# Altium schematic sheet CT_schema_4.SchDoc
size 454 x 430 mm
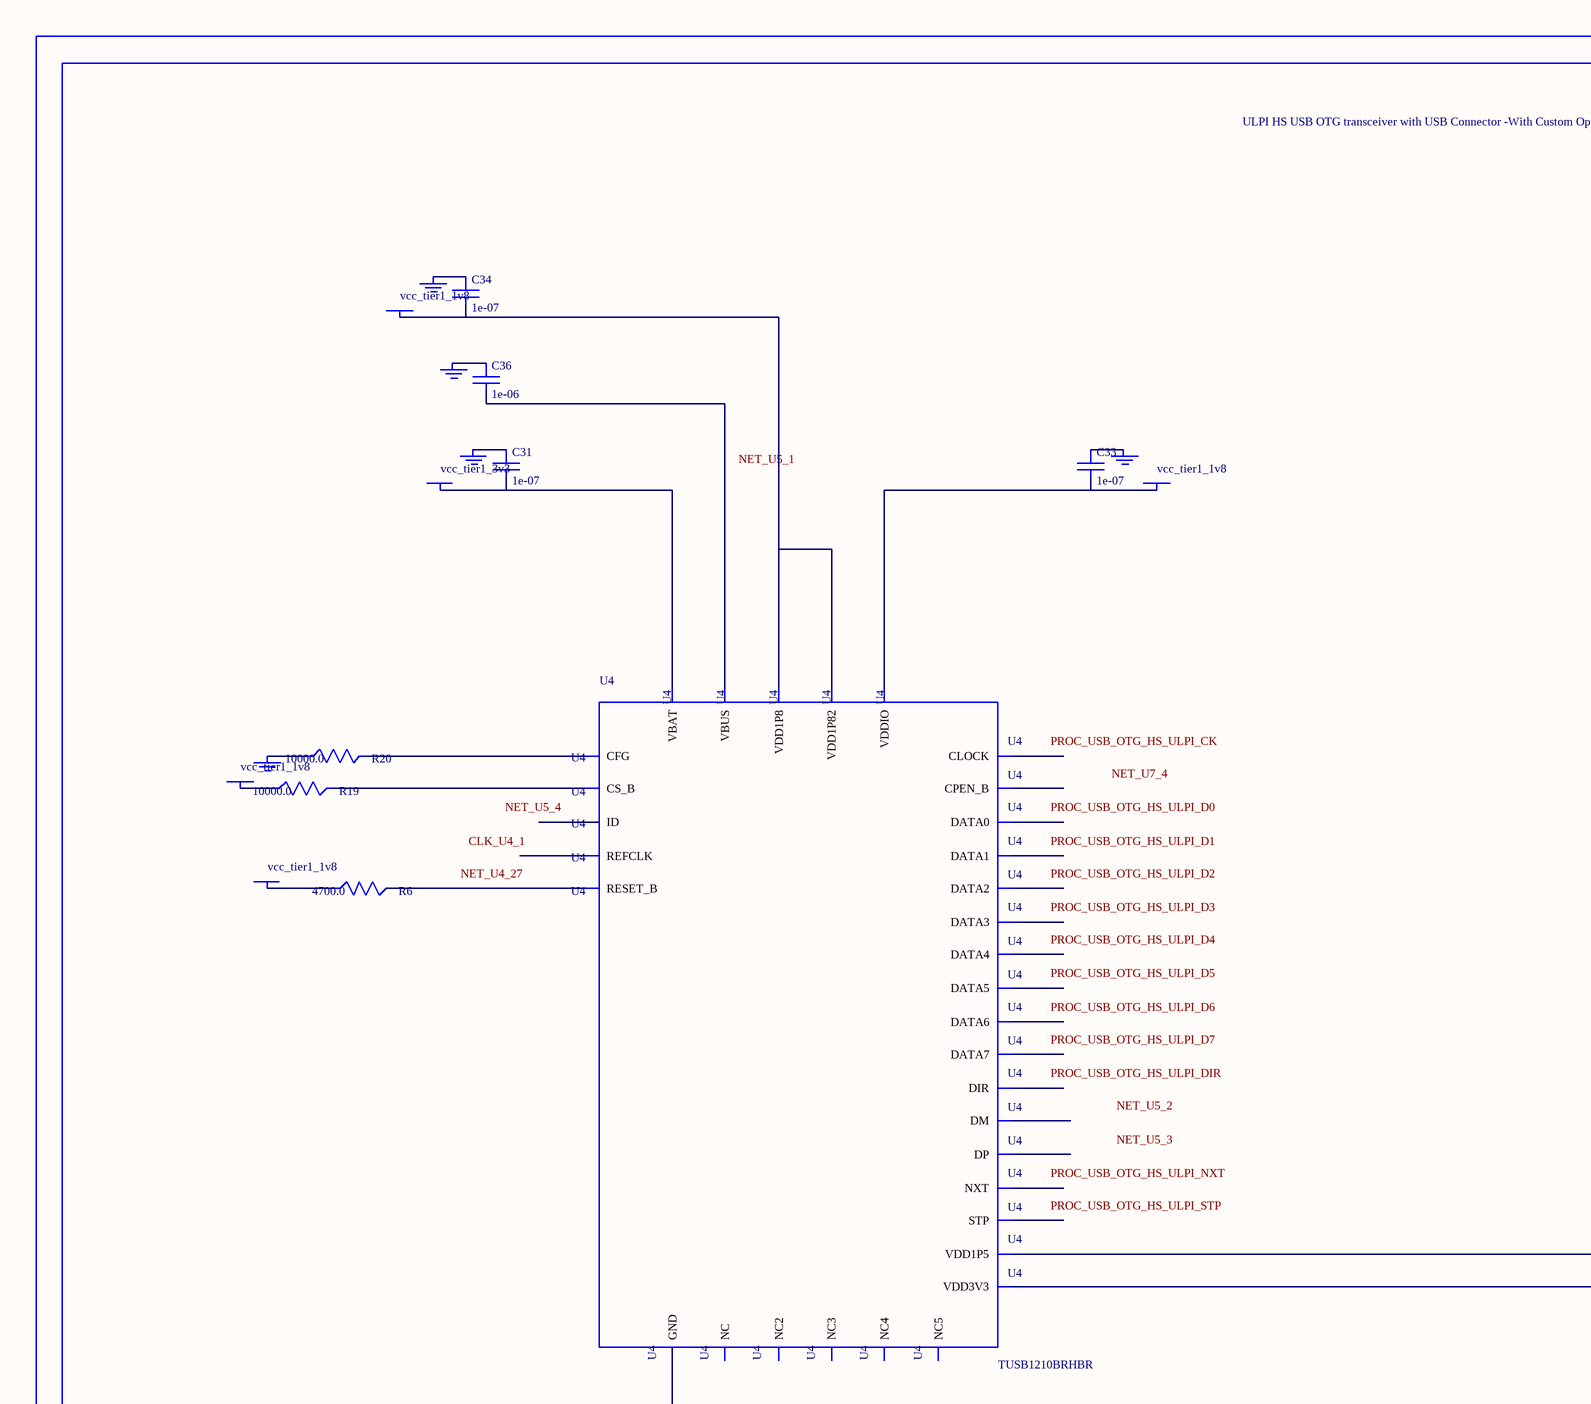
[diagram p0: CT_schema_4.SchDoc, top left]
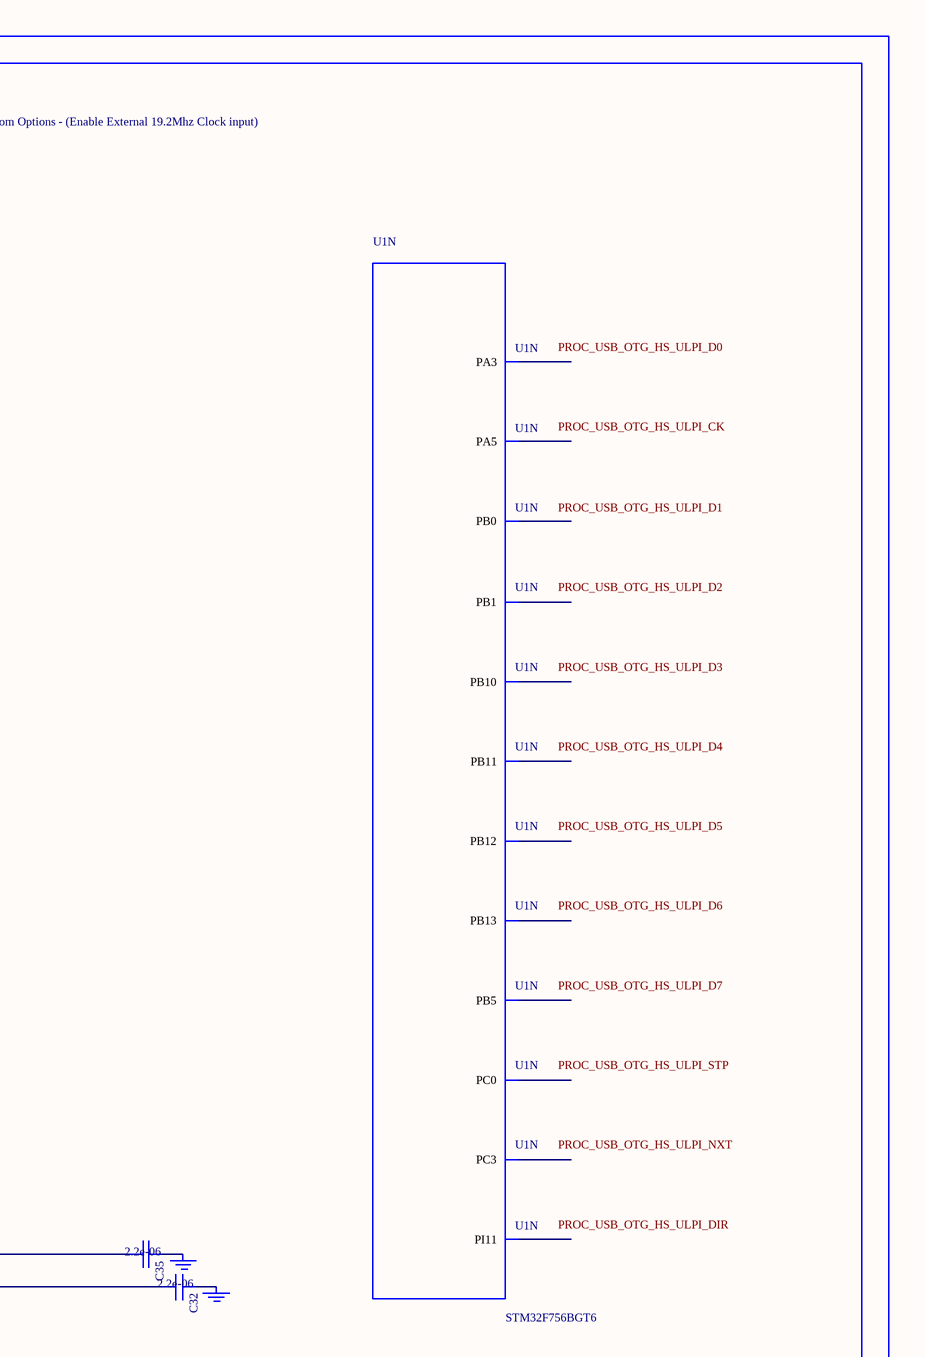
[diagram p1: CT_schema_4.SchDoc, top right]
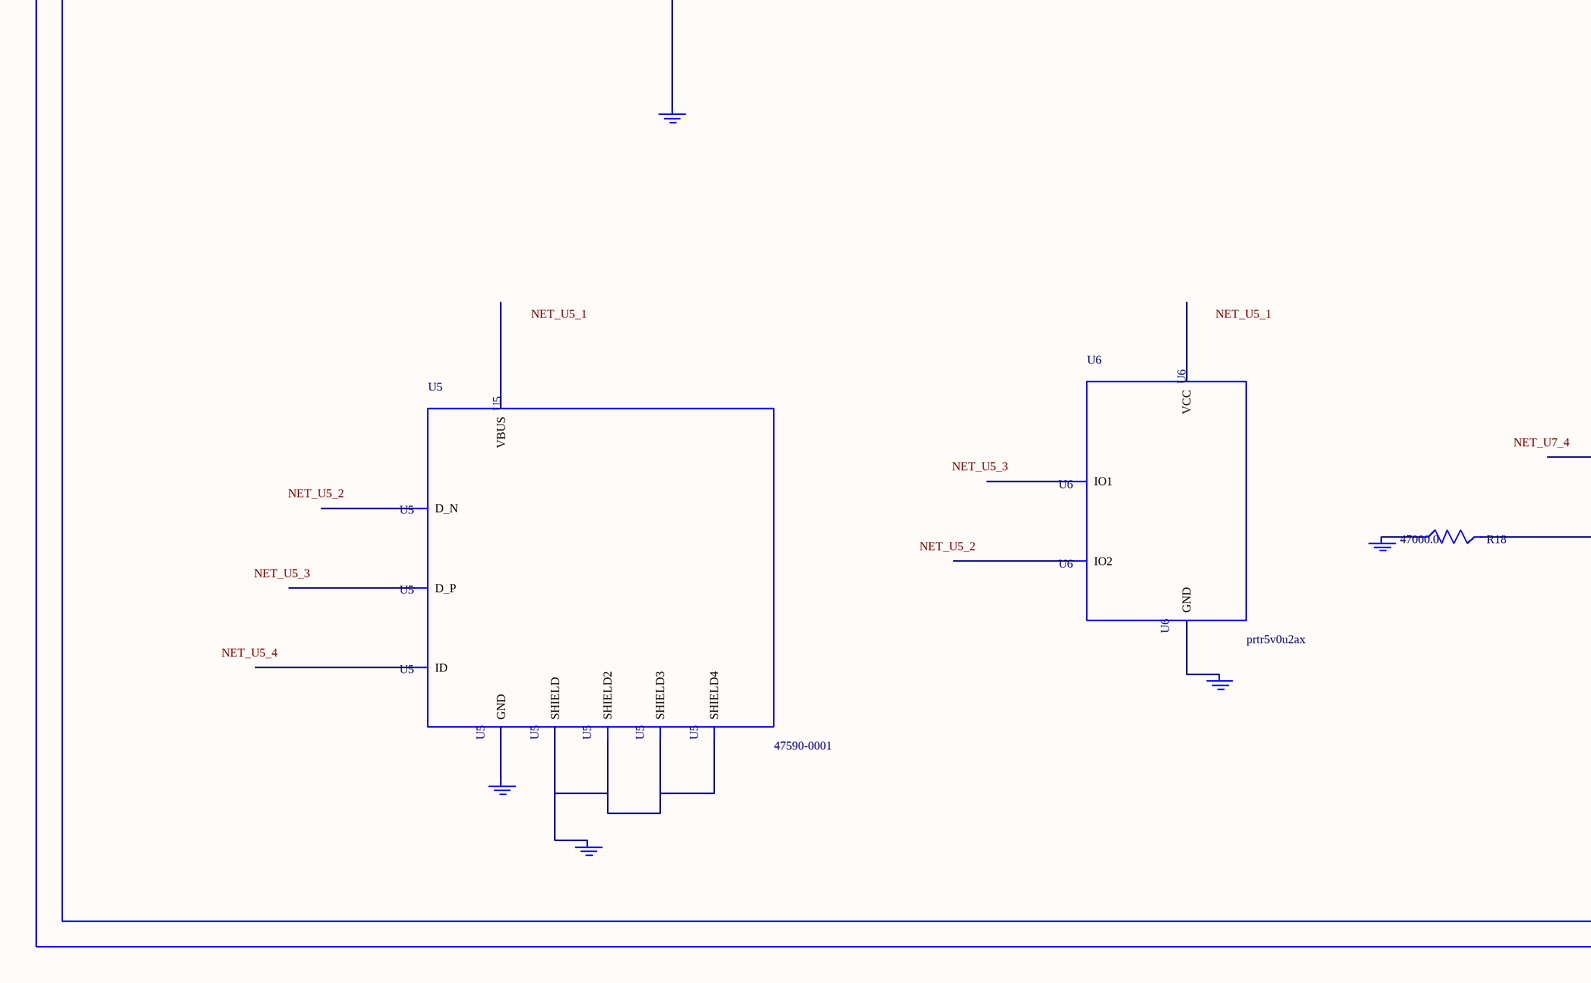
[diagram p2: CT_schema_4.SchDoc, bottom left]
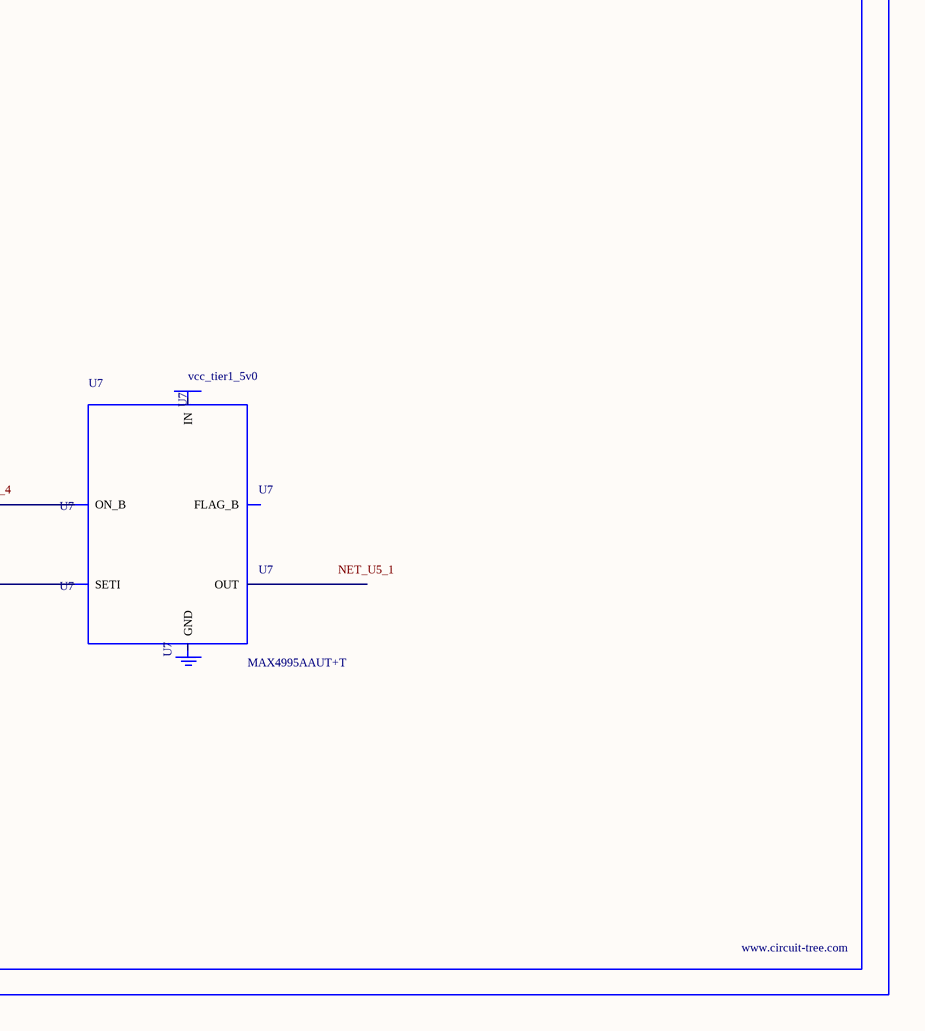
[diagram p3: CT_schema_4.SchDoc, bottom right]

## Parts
BORDER3  (no value)
C31  1e-07  [C0402]
C32  2.2e-06  [C0603]
C33  1e-07  [C0402]
C34  1e-07  [C0402]
C35  2.2e-06  [C0603]
C36  1e-06  [C0603]
GND_INSTANCE_3_0  (no value)
GND_INSTANCE_3_1  (no value)
GND_INSTANCE_3_2  (no value)
GND_INSTANCE_3_3  (no value)
GND_INSTANCE_3_4  (no value)
GND_INSTANCE_3_5  (no value)
GND_INSTANCE_3_6  (no value)
GND_INSTANCE_3_7  (no value)
GND_INSTANCE_3_8  (no value)
GND_INSTANCE_3_9  (no value)
GND_INSTANCE_3_10  (no value)
GND_INSTANCE_3_11  (no value)
GND_INSTANCE_3_12  (no value)
POWER_INSTANCE_3_0  vcc_tier1_1v8
POWER_INSTANCE_3_1  vcc_tier1_3v3
POWER_INSTANCE_3_2  vcc_tier1_1v8
POWER_INSTANCE_3_3  vcc_tier1_1v8
POWER_INSTANCE_3_4  vcc_tier1_1v8
POWER_INSTANCE_3_5  vcc_tier1_5v0
R6  4700.0  [R0603]
R18  47000.0  [R0603]
R19  10000.0  [R0603]
R20  10000.0  [R0603]
U1  STM32F756BGT6  [LQFP208]  (part N of 15)
U4  TUSB1210BRHBR  [RHB32_3P45X3P45]
U5  47590-0001  [MICRO_USB_AB]
U6  prtr5v0u2ax  [SOT143B]
U7  MAX4995AAUT+T  [SOT-23-6]

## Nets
NetC31_1: C31.1 GND_INSTANCE_3_3.0(GND)
NetC31_2: C31.2 POWER_INSTANCE_3_1.0(PWR) U4.21(VBAT)
NetC32_1: C32.1 GND_INSTANCE_3_2.0(GND)
NetC32_2: C32.2 U4.20(VDD3V3)
NetC33_1: C33.1 GND_INSTANCE_3_6.0(GND)
NetC33_2: C33.2 POWER_INSTANCE_3_3.0(PWR) U4.32(VDDIO)
NetC34_1: C34.1 GND_INSTANCE_3_5.0(GND)
NetC34_2: C34.2 POWER_INSTANCE_3_2.0(PWR) U4.28(VDD1P8) U4.30(VDD1P82)
NetC35_1: C35.1 GND_INSTANCE_3_0.0(GND)
NetC35_2: C35.2 U4.12(VDD1P5)
NetC36_1: C36.1 GND_INSTANCE_3_4.0(GND)
NetC36_2: C36.2 U4.22(VBUS)
NetGND_INSTANCE_3_1_0: GND_INSTANCE_3_1.0(GND) R20.1
NetGND_INSTANCE_3_7_0: GND_INSTANCE_3_7.0(GND) U4.33(GND)
NetGND_INSTANCE_3_8_0: GND_INSTANCE_3_8.0(GND) U5.6(SHIELD) U5.7(SHIELD2) U5.8(SHIELD3) U5.9(SHIELD4)
NetGND_INSTANCE_3_9_0: GND_INSTANCE_3_9.0(GND) U5.5(GND)
NetGND_INSTANCE_3_10_0: GND_INSTANCE_3_10.0(GND) U6.1(GND)
NetGND_INSTANCE_3_11_0: GND_INSTANCE_3_11.0(GND) R18.1
NetPOWER_INSTANCE_3_0_0: POWER_INSTANCE_3_0.0(PWR) R19.1
NetPOWER_INSTANCE_3_4_0: POWER_INSTANCE_3_4.0(PWR) R6.1
NetR6_2: R6.2 U4.27(RESET_B)
NetR18_2: R18.2 U7.3(SETI)
NetR19_2: R19.2 U4.11(CS_B)
NetR20_2: R20.2 U4.14(CFG)

Not connected (* = marked no-connect by the designer): GND_INSTANCE_3_12 0(GND); POWER_INSTANCE_3_5 0(PWR); U1 13(PI11) 35(PC0) 38(PC3) 50(PA3) 54(PA5) 61(PB0) 62(PB1) 90(PB10) 91(PB11) 104(PB12) 105(PB13) 194(PB5); U4 1(REFCLK) 2(NXT) 3(DATA0) 4(DATA1) 5(DATA2) 6(DATA3) 7(DATA4) 8(NC) 9(DATA5) 10(DATA6) 13(DATA7) 15(NC2) 16(NC3) 17(CPEN_B) 18(DP) 19(DM) 23(ID) 24(NC4) 25(NC5) 26(CLOCK) 29(STP) 31(DIR); U5 1(VBUS) 2(D_N) 3(D_P) 4(ID); U6 2(IO1) 3(IO2) 4(VCC); U7 1(OUT) 2(GND) 4(ON_B) 5(IN) 6(FLAG_B)

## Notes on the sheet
- Labels drawn without touching a wire or pin: CLK_U4_1, NET_U4_27, NET_U5_1, NET_U5_2, NET_U5_3, NET_U5_4, NET_U7_4, PROC_USB_OTG_HS_ULPI_CK, PROC_USB_OTG_HS_ULPI_D0, PROC_USB_OTG_HS_ULPI_D1, PROC_USB_OTG_HS_ULPI_D2, PROC_USB_OTG_HS_ULPI_D3, PROC_USB_OTG_HS_ULPI_D4, PROC_USB_OTG_HS_ULPI_D5, PROC_USB_OTG_HS_ULPI_D6, PROC_USB_OTG_HS_ULPI_D7, PROC_USB_OTG_HS_ULPI_DIR, PROC_USB_OTG_HS_ULPI_NXT, PROC_USB_OTG_HS_ULPI_STP

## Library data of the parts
BORDER3 = BORDER_PAGE3
C31 C33 C34 = C0402C104K3RACTU
C32 C35 = C0603C225K8RACTU
C36 = C0603C105K3RACTU
GND_INSTANCE_3_0-GND_INSTANCE_3_12 = GND
POWER_INSTANCE_3_0-POWER_INSTANCE_3_5 = PWR
R6 = RC0603JR-074K7L
R18 = RC0603JR-0747KL
R19 R20 = RC0603JR-0710KL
